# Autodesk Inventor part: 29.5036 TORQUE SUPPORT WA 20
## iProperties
Created: 2007-07
Part Number: 29.5036 TORQUE SUPPORT WA 20
Document SubType Name: Modeling
Designer: Andy Moles
Material: Steel
Density: 7.85 g/cm^3
Mass: 382.25 g
Surface Area: 232.547 cm^2
Volume: 48.6943 cm^3
Author: Andy Moles
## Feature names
1. Base1
